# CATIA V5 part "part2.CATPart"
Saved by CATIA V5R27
Part number: 3.29
Material "无"
Bounding box of the stored display mesh (mm): x -100 to 100, y -99.999 to 99.999, z -2.5 to 22.456
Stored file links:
  C:\Users\user\Desktop\180131229冯纪智\linjian.CATPart
  E:\Program Files\Dassault Systemes\B27\win_b64\startup\materials\yellow_env_512x512.jpg
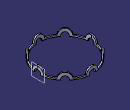
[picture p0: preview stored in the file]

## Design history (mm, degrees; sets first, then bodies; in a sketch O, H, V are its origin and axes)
Body1 (main body)
  Sketch1 on xy-plane, origin (0, 0, 0), H (1, 0, 0), V (0, 1, 0)
    circle A1 centre (0, 0) radius 100
    radius A1 = 100
  Pad1: profile Sketch1, direction (0, 0, 1), length 2.5, mirrored extent, thin wall 5
  Body2
    Sketch2 on xy-plane, origin (0, 0, 0), H (1, 0, 0), V (0, 1, 0)
      arc A1 centre (100, 0) radius 20 from (97.5, -19.8431) to (97.5, 19.8431) ccw
      point P1 (100, 0)
      axis line L1 (97.5, 70) -> (97.5, -80)
      point P2 (97.5, 70)
      point P4 (97.5, 19.8431)
      point P5 (97.5, -19.8431)
      radius A1 = 20
      distance P2 V = 97.5
      coincidence: P1 H, L1 P4, L1 P5
      vertical: L1 V
    Shaft1: profile Sketch2, axis Sketch2.L1, angle 360
    CircPattern1: of Shaft1, instances 8, angular step 45, axis from end face of Pad1
    Sketch3 on xy-plane, origin (0, 0, 0), H (1, 0, 0), V (0, 1, 0)
      circle A1 centre (0, 0) radius 95
      radius A1 = 95
    Pocket1: profile Sketch3, direction (0, 0, -1), length 30, mirrored extent
    Split1: SplitPlane start face of Pad1
    Sketch4 on xy-plane, origin (0, 0, 0), H (1, 0, 0), V (0, 1, 0)
      circle A1 centre (0, 0) radius 100
      radius A1 = 100
    Pocket2: profile Sketch4, direction (0, 0, -1), length 30, mirrored extent, outer side
  Assemble1: tool Body2
  Body3
    Plane1: type Offset, RefPlane yz-plane, Offset 97.5
    Sketch5 on Plane1, origin (97.5, 0, 0), H (0, 1, 0), V (0, 0, 1)
      arc A1 centre (0, 0) radius 12 from (-12, 0) to (12, 0) ccw
      axis line L1 (-20, 0) -> (20, 0)
      point P1 (-20, 0)
      point P3 (-12, 0)
      point P4 (12, 0)
      radius A1 = 12
      coincidence: P1 H, L1 P4, L1 P3
      horizontal: L1 H
    Shaft2: profile Sketch5, axis Sketch5.L1, angle 360
    CircPattern2: of the body so far, instances 8, angular step 45, axis from end face of Pad1
  Remove1: tool Body3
